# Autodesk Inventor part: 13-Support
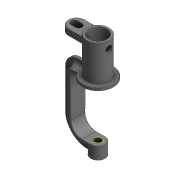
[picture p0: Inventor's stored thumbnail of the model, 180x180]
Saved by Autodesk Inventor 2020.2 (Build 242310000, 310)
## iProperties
Created: 2022-03
Part Number: 13-Support
Material: Fonte, moulé
Document SubType Name: Modeling
Designer: %USERNAME%
Density: 7.15 g/cm^3
Appearance: Gris clair
Author: %USERNAME%
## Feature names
1. Balayage1
2. Révolution1 [Revolution]
3. Extrusion1
4. Révolution2 [Revolution]
5. Congé1 [Fillet]
6. Extrusion2
7. Congé2 [Fillet]
8. Extrusion3
9. Révolution3 [Revolution]
10. Perçage2 [Hole]
11. Congé4 [Fillet]
12. Congé5 [Fillet]
## Parameters: d1 = 22 mm, d2 = 24 mm, d3 = 8.5 mm, d4 = 3 mm, d5 = 52.4 mm, d6 = 30.3 mm, d7 = 42 mm, d8 = 4.2 mm, d10 = 72.5 mm, d11 = 15 mm, d12 = 27 mm, d13 = 2 mm, d14 = 0, d15 = 4.2 mm, d16 = 19.3 mm, d17 = 4.2 mm, d18 = 15.5 mm, d19 = 0, d20 = 0, d21 = 90 deg, d22 = 22 mm, d23 = 0, d24 = 90 deg, d25 = 0, d26 = 0, d27 = -3.5 mm, d30 = 17 mm, d31 = 0, d32 = 6 mm, d41 = 6 mm, d42 = 9 mm, d44 = 17 mm, d45 = 0, d46 = 42 mm, d47 = 8.4 mm, d49 = 90 deg, d53 = 8.376 mm, d55 = 4 mm, d56 = 2 mm, d57 = 90 deg, d58 = 8 mm, d59 = 118 deg, d60 = 29 mm, d61 = 1 deg, d62 = -1 deg, d63 = 0.5 mm, d64 = 0.5 mm, d65 = 5 mm, d66 = 0.5 mm, d67 = 17.5 mm, d68 = 0, d69 = 0
